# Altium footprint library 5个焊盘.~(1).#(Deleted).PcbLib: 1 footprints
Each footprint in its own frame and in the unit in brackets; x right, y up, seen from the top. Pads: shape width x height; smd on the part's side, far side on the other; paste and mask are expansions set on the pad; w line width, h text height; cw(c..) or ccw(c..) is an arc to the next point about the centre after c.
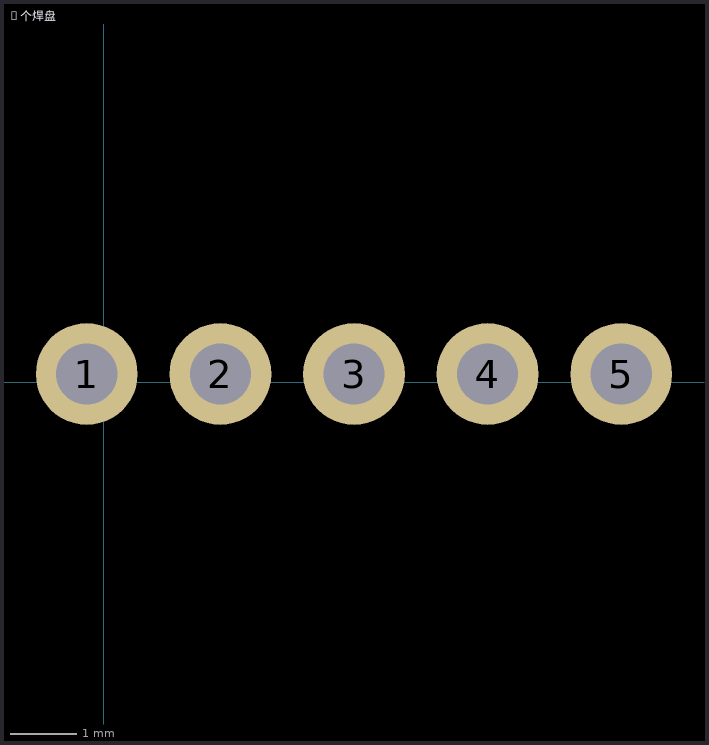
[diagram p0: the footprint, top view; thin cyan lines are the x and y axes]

## 5个焊盘 [mil]
pads (5):
  round 60 hole 36: 1(-10,5) 2(68.74,5) 3(147.48,5) 4(226.22,5) 5(304.96,5)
